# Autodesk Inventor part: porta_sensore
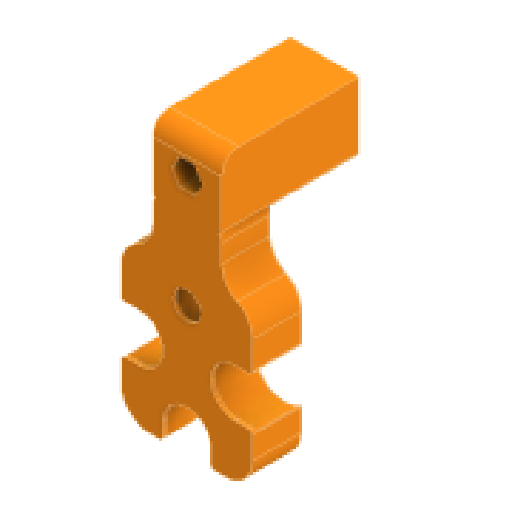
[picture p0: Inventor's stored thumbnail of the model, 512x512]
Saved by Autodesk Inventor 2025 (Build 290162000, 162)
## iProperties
Created: 2025-09
Part Number: porta_sensore
Material: Plastica ABS
Document SubType Name: Modeling
Designer: Ryzen5700u
Density: 1.06 g/cm^3
Appearance: Arancione
Author: Ryzen5700u
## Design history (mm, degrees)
sketch "Schizzo1"
  geometry: L1 (-10, -96)-(-10, 38) reference; L2 (9, -97)-(-9, -97) reference; L3 (10, 38)-(10, -96) reference; L4 (10, -97)-(-10, -97); L5 (-10, -97)-(-10, -77); L6 (-10, -77)-(10, -77); L7 (10, -77)-(10, -97); L8 (-10, 38)-(10, 38) reference; C1 r 2.25 at (0, -87) reference; A1 r 1 centre (-9, -96) between (-10, -96) and (-9, -97) reference; A2 r 1 centre (9, -96) between (9, -97) and (10, -96) reference; 7 further points
  constraints: 8 end point, 2 parallel, 1 horizontal, 1 perpendicular
  dimensions: "d0" = 20 distance of L5.end L6.end; "d1" = 20 distance of L4.end L5.end
extrude "Estrusione1" new body sketch "Schizzo1" distance "d2" = 40; taper "d3" = 0 deg
sketch "Schizzo2"
  geometry: L1 (1, 40)-(19, 40) reference; L2 (20, 40)-(0, 40); L3 (0, 40)-(0, 25); L4 (0, 25)-(20, 25); L5 (20, 25)-(20, 40); 5 further points
  constraints: 8 end point, 2 parallel, 1 horizontal, 1 perpendicular
  dimensions: "d4" = 20 distance of L4.end L3.end; "d5" = 15 distance of L3.end L2.end
extrude "Estrusione2" join sketch "Schizzo2" distance "d6" = 15; taper "d7" = 0 deg
sketch "Schizzo3"
  geometry: L1 (0, -15)-(20, -15) reference; L2 (10, -15)-(10, -78.397); L3 (20, -15)-(46.316, -15); L4 (0, -15)-(-26.316, -15); L5 (29, -15)-(-9, -15); L6 (-9, -15)-(-9, -60); L7 (-9, -60)-(29, -60); L8 (29, -60)-(29, -15); L9 (-9, -37.5)-(29, -37.5); L10 (-4, -28.5)-(-9, -28.5); L11 (24, -28.5)-(29, -28.5); L12 (-4, -46.5)-(-9, -46.5); L13 (1, -55)-(1, -60); L14 (19, -55)-(19, -60); L15 (24, -46.5)-(29, -46.5); C1 r 5.5 at (10, -22.614); A1 r 9 centre (-4, -37.5) between (-4, -28.5) and (-4, -46.5); A2 r 9 centre (24, -37.5) between (24, -28.5) and (24, -46.5); A3 r 9 centre (10, -55) between (1, -55) and (19, -55); 9 further points
  constraints: 28 end point, 13 point on line, 6 perpendicular, 6 point on circle, 4 centre point, 4 tangent, 3 midpoint, 2 horizontal, 2 parallel, 1 symmetric about line, 1 vertical, 1 other
  dimensions: "d28" = 45 distance of L6.end L5.end; "d29" = 38 distance of L6.end L7.end; "d30" = 18 diameter of A1; "d31" = 18 diameter of A2; "d32" = 5 distance from line of L6 A1.centre; "d33" = 5 distance from line of L8 A2.centre; "d34" = 11 diameter of C1; "d35" = 18 diameter of A3; "d36" = 5 distance from line of L7 A3.centre
extrude "Estrusione3" join sketch "Schizzo3" distance "d16" = 15; taper "d17" = 0 deg
sketch "Schizzo4"
  geometry: L1 (10, -77)-(-10, -77) reference; 2 further points
  dimensions: "d18" = 10 distance from line of L1 point (0, -87)
hole "Foro1" sketch "Schizzo4" at (0, -87) diameter "d19" = 4.5; stored, may be unused: countersink angle "d23" = 90 deg, drill point angle "d25" = 118 deg; dims "d20" = 6, "d21" = 8, "d22" = 20, "d24" = 8
sketch "Schizzo5"
  geometry: L1 (-10, -77)-(-10, -96) reference; L2 (-10, -112)-(-19, -112) reference; L3 (-19, -141.983)-(-19, -157) reference; L4 (-19, -112)-(-19, -127.017) reference; L5 (7.483, -157)-(19, -157) reference; L6 (-19, -157)-(-7.483, -157) reference; L7 (19, -127.017)-(19, -112) reference; L8 (19, -157)-(19, -141.983) reference; L9 (19, -112)-(10, -112) reference; L10 (10, -97)-(10, -112) reference; L11 (-14, -141.5)-(-19, -141.5); L12 (-19, -141.5)-(-19, -143.5); L13 (-14, -127.5)-(-19, -127.5); L14 (-19, -127.5)-(-19, -125.5); L15 (14, -127.5)-(19, -127.5); L16 (19, -127.5)-(19, -125.5); L17 (14, -141.5)-(19, -141.5); L18 (19, -143.5)-(19, -141.5); L19 (7, -152)-(7, -157); L20 (7, -157)-(9, -157); L21 (-7, -152)-(-7, -157); L22 (-7, -157)-(-9, -157); L23 (-9, -97)-(-10, -97) reference; L24 (-10, -97)-(-10, -112) reference; L25 (10, -97)-(9, -97) reference; L26 (10, -96)-(10, -77) reference; L27 (10, -77)-(-10, -77) reference; C1 r 5.5 at (0, -119.614) reference; C2 r 4 at (0, -119.614); A1 r 9 centre (-14, -134.5) between (-19, -141.983) and (-19, -127.017) reference; A2 r 9 centre (0, -152) between (7.483, -157) and (-7.483, -157) reference; A3 r 9 centre (14, -134.5) between (19, -127.017) and (19, -141.983) reference; A4 r 7 centre (0, -152) between (7, -152) and (-7, -152); A5 r 7 centre (-14, -134.5) between (-14, -141.5) and (-14, -127.5); A6 r 7 centre (14, -134.5) between (14, -127.5) and (14, -141.5); A7 r 1 centre (-9, -96) between (-10, -96) and (-9, -97) reference; A8 r 1 centre (9, -96) between (9, -97) and (10, -96) reference; 8 further points
  constraints: 24 end point, 8 point on line, 7 perpendicular, 6 point on circle, 4 centre point, 4 coincident, 4 tangent, 1 horizontal, 1 parallel
  dimensions: "d37" = 14 diameter of A4; "d38" = 14 diameter of A5; "d39" = 14 diameter of A6; "d40" = 8 diameter of C2
extrude "Estrusione4" join sketch "Schizzo5" distance "d41" = 1; taper "d42" = 0 deg
fillet "Raccordo3" dims "d43" = 8
chamfer "Smusso1" distance "d44" = 1; stored, may be unused: second distance "d45" = 2, angle "d46" = 45 deg
fillet "Raccordo4" dims "d47" = 1
sketch "Schizzo6"
  geometry: L1 (4.4, -87)-(2.2, -90.811); L2 (2.2, -90.811)-(-2.2, -90.811); L3 (-2.2, -90.811)-(-4.4, -87); L4 (-4.4, -87)-(-2.2, -83.189); L5 (-2.2, -83.189)-(2.2, -83.189); L6 (2.2, -83.189)-(4.4, -87); C1 r 2.25 at (0, -87) reference; 2 further points
  constraints: 12 end point, 13 other
  dimensions: "d51" = 4.4 distance of L1.end L2.end
extrude "Estrusione5" cut sketch "Schizzo6" distance "d48" = 20; taper "d49" = 0 deg
fillet "Raccordo5" dims "d52" = 2
fillet "Raccordo6" dims "d53" = 5
node "Solido1"
node "Riferimento1"
node "Linea chiusa proiettata1"
